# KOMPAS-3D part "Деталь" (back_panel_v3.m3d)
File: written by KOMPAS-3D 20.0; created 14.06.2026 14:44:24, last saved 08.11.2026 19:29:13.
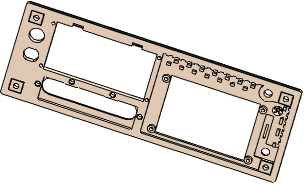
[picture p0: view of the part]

Document properties: Полное имя файла: D:\myProjects\Progect_esp32\box_compas\корпус\back_panel_v3.m3d

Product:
- Part/product: Деталь
    Материал: Фанера, береза,ФСФ ВВ/С ГОСТ 3916.1-2018 (density 760 kg/m3)
    Масса: 0.0216848

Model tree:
1. Эскиз:1
2. Элемент выдавливания:1
     Расстояние 1 = 4
3. Эскиз:5  (with: Элемент выдавливания:1)
4. Элемент выдавливания:5
     Расстояние 2 = 2
5. Эскиз:6  (with: Элемент выдавливания:1, Элемент выдавливания:5)
6. Эскиз:4  (with: Элемент выдавливания:1)
7. Элемент выдавливания:6
     Расстояние 2 = 4
8. Массив по сетке:14  (with: Элемент выдавливания:6, Эскиз:6)  (4 pattern instances)
     Шаг 1 = 196; Угол раствора = -90; Шаг 2 = 60
9. Эскиз:16  (with: Элемент выдавливания:1)
10. Элемент выдавливания:19
     Расстояние 2 = 4
11. Эскиз:17  (with: Элемент выдавливания:1, Элемент выдавливания:19)
12. Элемент выдавливания:23
     Расстояние 2 = 4
13. Эскиз:20  (with: Элемент выдавливания:5, Элемент выдавливания:19)
14. Элемент выдавливания:24
     Расстояние 2 = 1.5
15. Скругление:7  (with: Элемент выдавливания:24)
     Радиус = 3
16. Эскиз:22  (with: Элемент выдавливания:5)
17. Элемент выдавливания:26
     Расстояние 1 = 2
18. Скругление:8  (with: Элемент выдавливания:26)
     Радиус = 0.4
19. Массив по сетке:5  (with: Элемент выдавливания:26, Эскиз:22, Скругление:8, Элемент выдавливания:5)  (7 pattern instances)
     Шаг 1 = 5; Угол раствора = 90
20. Эскиз:25  (with: Элемент выдавливания:5)
21. Элемент выдавливания:28
     Расстояние 1 = 2
22. Скругление:10  (with: Элемент выдавливания:28)
     Радиус = 0.4
23. Массив по сетке:7  (with: Элемент выдавливания:28, Эскиз:25, Скругление:10, Элемент выдавливания:5)  (15 pattern instances)
     Шаг 1 = 5; Угол раствора = 90
24. Массив по концентрической сетке:3  (with: Элемент выдавливания:23, Эскиз:17, Элемент выдавливания:19)  (5 pattern instances)
     Шаг 2 = 360
25. Эскиз:29  (with: Элемент выдавливания:5, Элемент выдавливания:1)
26. Элемент выдавливания:36
     Расстояние 2 = 2
27. Смещенная плоскость:1  (with: Элемент выдавливания:1)
     Расстояние = 13.75
28. Эскиз:32  (with: Элемент выдавливания:36)
29. Элемент вращения:3
     Угол 1 = 360
30. Элемент выдавливания:46
     Расстояние 2 = 4
31. Эскиз:2  (with: Элемент выдавливания:1, Элемент выдавливания:46)
32. Элемент выдавливания:2
     Расстояние 2 = 4
33. Массив по сетке:1  (with: Элемент выдавливания:2, Эскиз:2)  (4 pattern instances)
     Шаг 1 = 83; Угол раствора = 90; Шаг 2 = 37
34. Эскиз:39  (with: Элемент выдавливания:1, Элемент выдавливания:46)
35. Элемент выдавливания:48
     Расстояние 2 = 4
36. Массив по сетке:11  (with: Элемент выдавливания:48, Эскиз:39, Элемент выдавливания:1)  (4 pattern instances)
     Шаг 1 = 75.9; Угол раствора = 90; Шаг 2 = 44.2
37. Эскиз:35  (with: Элемент выдавливания:5, Элемент выдавливания:2, Скругление:7, Элемент выдавливания:26, Скругление:8, Элемент выдавливания:28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)
38. Элемент выдавливания:50
     Расстояние 1 = 2
39. Эскиз:41  (with: Элемент выдавливания:5, Элемент выдавливания:48)
40. Элемент выдавливания:52
     Расстояние 1 = 2
41. Эскиз:42  (with: Элемент выдавливания:1, Элемент выдавливания:46)
42. Элемент выдавливания:55
     Расстояние 2 = 4
43. Эскиз:45  (with: Элемент выдавливания:5)
44. Элемент выдавливания:58
     Расстояние 1 = 2
45. Массив по сетке:12  (with: Элемент выдавливания:58, Эскиз:45)  (3 pattern instances)
     Шаг 1 = 10; Угол раствора = -90
46. Эскиз:46  (with: Элемент выдавливания:5, Элемент выдавливания:1)
47. Элемент выдавливания:59
     Расстояние 1 = 2
48. Массив по сетке:13  (with: Элемент выдавливания:59, Эскиз:46, Элемент выдавливания:1)  (7 pattern instances)
     Шаг 1 = 10; Угол раствора = 90
49. Эскиз:47  (with: Элемент выдавливания:5, Элемент выдавливания:1)
50. Элемент выдавливания:60
     Расстояние 2 = 0.75
51. Фаска:1  (with: Элемент выдавливания:48, Элемент выдавливания:2)
     Угол = 45; Длина 1 = 0.75; Длина 2 = 0.75
52. Эскиз:49  (with: Элемент выдавливания:1, Элемент выдавливания:6, Элемент выдавливания:19, Элемент выдавливания:23, Элемент выдавливания:36, Элемент выдавливания:46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)
53. Эскиз:52  (with: Элемент выдавливания:1, Элемент выдавливания:55)
54. Элемент выдавливания:63
     Расстояние 2 = 2
55. Эскиз:53  (with: Элемент выдавливания:1)
56. Элемент выдавливания:64
     Расстояние 2 = 0.2
57. Скругление:15  (with: Элемент выдавливания:63)
     Радиус = 1
58. Массив по сетке:15  (with: Элемент выдавливания:64, Эскиз:53)  (4 pattern instances)
     Шаг 1 = 196; Угол раствора = -90; Шаг 2 = 60
59. Фаска:2  (with: Элемент выдавливания:50)
     Угол = 45; Длина 1 = 0.4; Длина 2 = 0.4
60. Эскиз:54  (with: Элемент выдавливания:1, Элемент выдавливания:50, Элемент выдавливания:55, Фаска:2)
61. Элемент выдавливания:67
     Расстояние 2 = 2.5
62. Скругление:16  (with: Элемент выдавливания:67, Элемент выдавливания:50, Элемент выдавливания:5)
     Радиус = 1
63. Скругление:17  (with: Элемент выдавливания:1)
     Радиус = 1
64. Скругление:18  (with: Элемент выдавливания:1)  (labels: Фанера, береза,ФСФ ВВ/С ГОСТ 3916.1-2018)
     Радиус = 2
